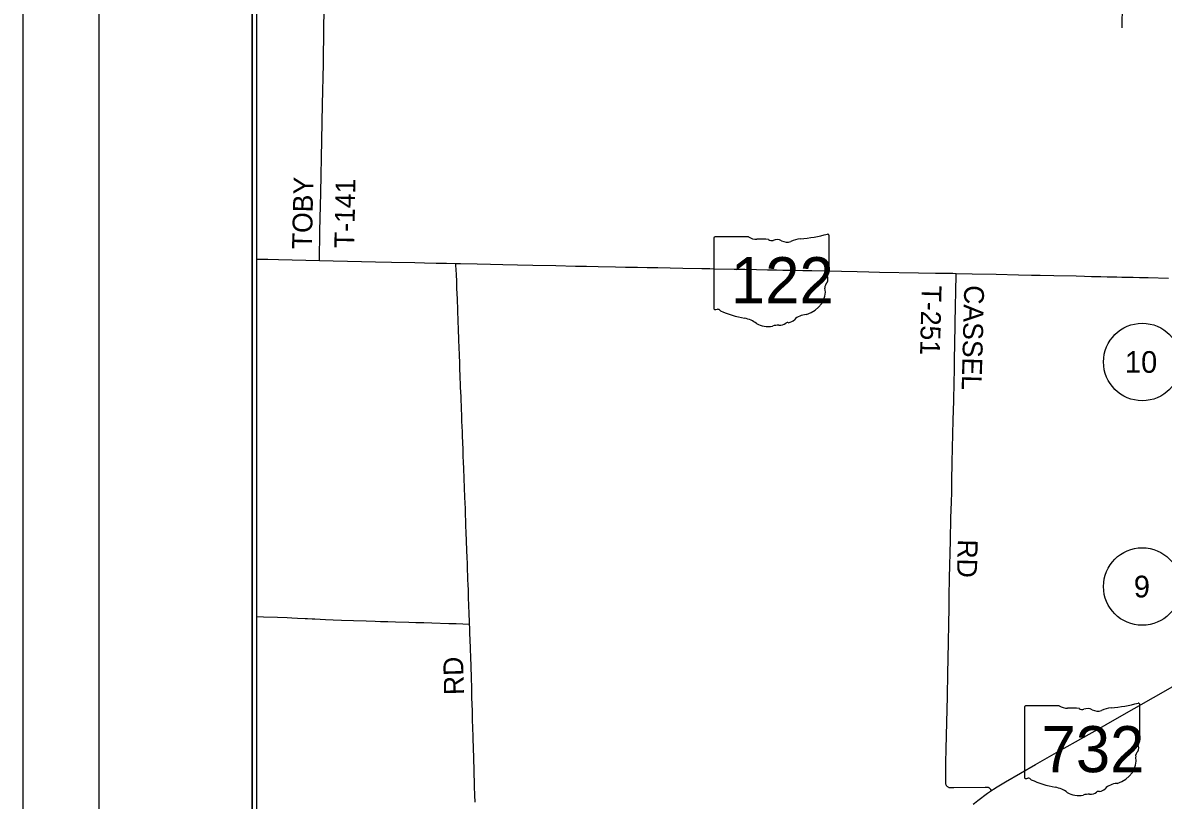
# Model space of a CAD drawing. Extents: x 1341221 to 1914484, y 79347 to 658398.
# Drawn here: x 1341221 to 1374791, y 599399 to 622283 of the extents above; entities that cross this region are included whole.
import ezdxf

# ---------------------------------------------------------------- set-up
doc = ezdxf.new("R2010")
doc.units = 0
for name, color, linetype in [('GM_X_Corporation_Text', 7, 'Continuous'), ('GM_X_County', 7, 'Continuous'), ('GM_X_Major_Lake_Text', 7, 'Continuous'), ('GM_X_Major_River', 7, 'Continuous'), ('GM_X_Major_River_Text', 7, 'Continuous'), ('GM_X_Minor_Lake_Text', 7, 'Continuous'), ('GM_X_Minor_River_Text', 7, 'Continuous'), ('GM_X_State_Location', 7, 'Continuous'), ('GM_X_State_Shield', 7, 'Continuous'), ('GM_X_Township_Text', 7, 'Continuous'), ('GM_X_US_Shield', 7, 'Continuous')]:
    doc.layers.add(name, color=color, linetype=linetype)

msp = doc.modelspace()

# ---------------------------------------------------------------- linework, layer by layer
at = {"layer": 'GM_X_Corporation_Text'}
for p, q in [((1364953, 614951), (1364953, 616029)), ((1361559, 615942), (1361559, 613882)), ((1362586, 615978), (1361593, 615978)), ((1364952, 614951), (1364953, 614951)), ((1370705, 602137), (1370705, 600077)), ((1371733, 602172), (1370739, 602172)), ((1374099, 601146), (1374099, 602223)), ((1374098, 601146), (1374099, 601146))]:
    msp.add_line(p, q, dxfattribs=at)
for centre, major_axis, start_param, end_param in [((1363744, 618787), (3599, 0), 4.814394, 5.042369), ((1364915, 616033), (37.8, 0), 6.141152, 7.989035), ((1361598, 615947), (39.3, 0), 1.712693, 3.28349), ((1362823, 616217), (381, 0), 4.042523, 4.731795), ((1362949, 614821), (1369, 0), 1.404758, 1.657858), ((1363260, 615957), (110, 0), 3.836095, 5.185415), ((1363422, 615719), (229, 0), 0.950623, 2.079405), ((1363717, 616046), (275, 0), 4.081561, 5.145723), ((1364203, 615348), (724, 0), 1.699011, 2.107814), ((1364944, 614872), (58.5, 0), 1.883978, 3.671073), ((1364572, 614735), (351, 0), 5.934695, 6.695948), ((1364912, 614947), (40.4, 0), 5.05454, 6.418171), ((1363945, 614363), (900, 0), 5.101752, 6.440018), ((1365088, 614500), (255, 0), 2.387724, 3.262537), ((1361598, 613877), (39.7, 0), 3.00124, 4.508301), ((1361604, 614088), (303, 0), 4.665946, 4.897461), ((1361666, 613763), (109, 0), 0.519207, 1.627899), ((1363044, 615614), (2599, 0), 4.195997, 4.488961), ((1364325, 613303), (493, 0), 1.647645, 2.488434), ((1362269, 612956), (813, 0), 0.823519, 1.323587), ((1363149, 613753), (516, 0), 4.026481, 4.996735), ((1363447, 613040), (424, 0), 1.495662, 1.94098), ((1363485, 613598), (275, 0), 4.691044, 5.507374), ((1363733, 613399), (77.4, 0), 1.147584, 2.315152), ((1363700, 613682), (291, 0), 4.937069, 5.64225), ((1372890, 604981), (3599, 0), 4.814394, 5.042369), ((1374061, 602228), (37.8, 0), 6.141152, 7.989035), ((1370744, 602141), (39.3, 0), 1.712693, 3.28349), ((1371969, 602412), (381, 0), 4.042523, 4.731795), ((1372096, 601016), (1369, 0), 1.404758, 1.657858), ((1372406, 602152), (110, 0), 3.836095, 5.185415), ((1372568, 601914), (229, 0), 0.950623, 2.079405), ((1372863, 602241), (275, 0), 4.081561, 5.145723), ((1373349, 601543), (724, 0), 1.699011, 2.107814), ((1374090, 601066), (58.5, 0), 1.883978, 3.671073), ((1373718, 600930), (351, 0), 5.934695, 6.695948), ((1374059, 601141), (40.4, 0), 5.05454, 6.418171), ((1373092, 600557), (900, 0), 5.101752, 6.440018), ((1374234, 600695), (255, 0), 2.387724, 3.262537), ((1370745, 600072), (39.7, 0), 3.00124, 4.508301), ((1370751, 600283), (303, 0), 4.665946, 4.897461), ((1370813, 599958), (109, 0), 0.519207, 1.627899), ((1372190, 601809), (2599, 0), 4.195997, 4.488961), ((1371416, 599151), (813, 0), 0.823519, 1.323587), ((1372295, 599947), (516, 0), 4.026481, 4.996735), ((1372593, 599235), (424, 0), 1.495662, 1.94098), ((1372631, 599793), (275, 0), 4.691044, 5.507374), ((1372880, 599594), (77.4, 0), 1.147584, 2.315152), ((1372847, 599877), (291, 0), 4.937069, 5.64225), ((1373471, 599498), (493, 0), 1.647645, 2.488434)]:
    msp.add_ellipse(centre, major_axis=major_axis, ratio=0.8, start_param=start_param, end_param=end_param, dxfattribs=at)
at = {"layer": 'GM_X_County'}
for centre in [(1374174, 612298), (1374174, 605688)]:
    msp.add_circle(centre, 1141, dxfattribs=at)
at = {"layer": 'GM_X_Minor_Lake_Text'}
for points in [[(1343471, 656148), (1347971, 656148), (1347971, 561648), (1343471, 561648)], [(1347971, 656148), (1491971, 656148), (1491971, 561648), (1347971, 561648)], [(1435650, 641695), (1348099, 641695), (1348099, 580425), (1435650, 580425)]]:
    msp.add_lwpolyline(points, close=True, dxfattribs=at)
at = {"layer": 'GM_X_Minor_River_Text'}
msp.add_lwpolyline([(1341221, 559398), (1494221, 559398), (1494221, 658398), (1341221, 658398)], close=True, dxfattribs=at)
at = {"layer": 'GM_X_State_Location'}
for p, q in [((1373403, 614802), (1373423, 614802)), ((1373711, 614796), (1373762, 614796))]:
    msp.add_line(p, q, dxfattribs=at)
for points in [[(1348099, 615327), (1348431, 615321), (1348744, 615314), (1349956, 615283)], [(1349956, 615283), (1350359, 615275), (1350774, 615266), (1351600, 615248), (1352073, 615239), (1352757, 615225), (1353045, 615220), (1353390, 615211), (1353691, 615204), (1353969, 615198), (1354106, 615195), (1354593, 615187), (1354989, 615176), (1355347, 615168), (1355788, 615156), (1356236, 615147), (1356914, 615134), (1357490, 615123), (1357816, 615117), (1358154, 615110), (1358672, 615097), (1358960, 615093), (1359318, 615089), (1359600, 615082), (1359913, 615077), (1360278, 615068), (1360655, 615060), (1361205, 615051), (1361442, 615047)], [(1361442, 615047), (1361576, 615045), (1362164, 615034), (1362478, 615027), (1362817, 615021), (1363143, 615012), (1363405, 615007), (1363597, 615003), (1363897, 614998), (1364185, 614993), (1364447, 614988), (1364844, 614979), (1365323, 614968), (1365784, 614960), (1366123, 614954), (1366443, 614947), (1367588, 614927), (1368086, 614916), (1368598, 614908), (1368699, 614906)], [(1368699, 614906), (1369167, 614897), (1369871, 614882), (1370536, 614867), (1370913, 614858), (1371169, 614853), (1371572, 614844), (1372230, 614830), (1372473, 614823), (1372678, 614818), (1372953, 614813), (1373145, 614809), (1373403, 614802)], [(1373423, 614802), (1373577, 614798), (1373711, 614796)], [(1373762, 614796), (1373905, 614792), (1374090, 614789), (1374346, 614781), (1374947, 614768)], [(1369197, 599284), (1369239, 599316), (1369336, 599389), (1369617, 599601), (1369739, 599687), (1369792, 599722), (1369899, 599790), (1370152, 599941), (1371027, 600446), (1371722, 600842), (1372205, 601120), (1372852, 601483), (1373372, 601772), (1375078, 602744), (1375736, 603114), (1375804, 603153), (1376176, 603363), (1376498, 603548), (1376965, 603813), (1377238, 603969), (1378266, 604560), (1378605, 604754)]]:
    msp.add_lwpolyline(points, dxfattribs=at)
at = {"layer": 'GM_X_State_Shield'}
msp.add_lwpolyline([(1373583, 622133), (1373584, 622196), (1373586, 622363), (1373592, 622600), (1373597, 622741), (1373600, 622916), (1373604, 623056), (1373609, 623174), (1373614, 623347), (1373625, 623774), (1373632, 624099), (1373634, 624190), (1373636, 624273)], dxfattribs=at)
at = {"layer": 'GM_X_Township_Text'}
msp.add_line((1349604, 604745), (1349737, 604739), dxfattribs=at)
for points in [[(1349956, 615283), (1349968, 616145), (1349990, 617280), (1350024, 618829), (1350044, 619881), (1350068, 621073), (1350085, 622141), (1350105, 623129), (1350108, 623348), (1350116, 623891), (1350128, 624506), (1350151, 625514), (1350155, 625698), (1350177, 626717), (1350194, 627898), (1350210, 628758), (1350238, 629801), (1350245, 630358), (1350258, 630899)], [(1369739, 599687), (1369713, 599718), (1369696, 599736), (1369684, 599747), (1369677, 599754), (1369669, 599759), (1369661, 599763), (1369655, 599766), (1369646, 599769), (1369640, 599770), (1369631, 599772), (1369618, 599774), (1369597, 599775), (1369554, 599775), (1368623, 599763), (1368569, 599763), (1368544, 599762), (1368534, 599763), (1368519, 599763), (1368509, 599765), (1368495, 599767), (1368479, 599772), (1368462, 599779), (1368447, 599788), (1368432, 599801), (1368420, 599815), (1368413, 599827), (1368406, 599839), (1368402, 599853), (1368397, 599872), (1368395, 599891), (1368394, 599917), (1368393, 599966), (1368396, 600173), (1368396, 600506), (1368404, 600896), (1368413, 601299), (1368438, 602450), (1368451, 603134), (1368461, 603563), (1368489, 605072), (1368494, 605399), (1368504, 605942), (1368532, 607042), (1368544, 607707), (1368560, 608175), (1368568, 608468), (1368572, 608793), (1368582, 609346), (1368612, 610585), (1368627, 611154), (1368637, 611704), (1368643, 612056), (1368652, 612439), (1368659, 612765), (1368670, 613457), (1368698, 614851), (1368699, 614906)], [(1348099, 604807), (1348308, 604800), (1348723, 604784), (1349005, 604773), (1349139, 604767), (1349309, 604759), (1349532, 604749), (1349604, 604745)], [(1349737, 604739), (1349816, 604734), (1350136, 604720), (1350359, 604710), (1350601, 604701), (1350953, 604689), (1351326, 604675), (1351596, 604667), (1351751, 604663), (1351967, 604656), (1352187, 604649), (1352583, 604637), (1352792, 604631), (1353023, 604625), (1353261, 604618), (1353766, 604602), (1353973, 604596), (1354177, 604590), (1354372, 604585)]]:
    msp.add_lwpolyline(points, dxfattribs=at)
at = {"layer": 'GM_X_US_Shield'}
msp.add_lwpolyline([(1354536, 599343), (1354530, 599542), (1354522, 599803), (1354518, 599939), (1354511, 600163), (1354505, 600348), (1354499, 600554), (1354494, 600710), (1354489, 600865), (1354484, 601012), (1354480, 601141), (1354474, 601338), (1354470, 601459), (1354467, 601566), (1354463, 601721), (1354458, 601870), (1354454, 602016), (1354443, 602425), (1354440, 602587), (1354435, 602782), (1354432, 602923), (1354425, 603100), (1354420, 603247), (1354417, 603372), (1354416, 603438), (1354413, 603508), (1354412, 603559), (1354409, 603615), (1354401, 603836), (1354388, 604160), (1354384, 604263), (1354380, 604364), (1354376, 604472), (1354372, 604585), (1354370, 604663), (1354362, 604889), (1354353, 605136), (1354345, 605352), (1354336, 605583), (1354329, 605750), (1354324, 605885), (1354317, 606055), (1354315, 606128), (1354307, 606349), (1354299, 606565), (1354293, 606733), (1354281, 607050), (1354273, 607257), (1354265, 607493), (1354260, 607619), (1354254, 607803), (1354249, 607957), (1354239, 608173), (1354234, 608285), (1354229, 608402), (1354224, 608519), (1354221, 608603), (1354211, 608854), (1354199, 609170), (1354194, 609341), (1354186, 609538), (1354180, 609726), (1354165, 610120), (1354161, 610243), (1354154, 610397), (1354148, 610559), (1354141, 610739), (1354135, 610895), (1354122, 611272), (1354110, 611559), (1354095, 611926), (1354090, 612059), (1354082, 612252), (1354073, 612516), (1354065, 612716), (1354057, 612948), (1354044, 613275), (1354036, 613492), (1354025, 613823), (1354012, 614156), (1354000, 614465), (1353995, 614583), (1353993, 614678), (1353986, 614861), (1353978, 615023), (1353972, 615140), (1353971, 615173), (1353969, 615198)], dxfattribs=at)

# ---------------------------------------------------------------- texts
at = {"layer": 'GM_X_Corporation_Text'}
for s, p in [('122', (1362064, 614027)), ('732', (1371210, 600222))]:
    msp.add_text(s, height=1357.4, dxfattribs=at).set_placement(p)
at = {"layer": 'GM_X_County'}
for s, height, p in [('10', 638.8, (1373665, 611979)), ('9', 639, (1373926, 605368))]:
    msp.add_text(s, height=height, dxfattribs=at).set_placement(p)
at = {"layer": 'GM_X_Major_Lake_Text'}
msp.add_text('RD', height=585, rotation=91.4816, dxfattribs=at).set_placement((1354208, 602501))
at = {"layer": 'GM_X_Major_River'}
for s, p in [('s', (1363218, 614775)), ('r', (1363218, 614775)), ('s', (1372364, 600970)), ('r', (1372364, 600970))]:
    msp.add_text(s, height=1.95, dxfattribs=at).set_placement(p)
for s, p in [('122', (1362529, 614633)), ('732', (1371676, 600828))]:
    msp.add_text(s, height=1.95, rotation=0, dxfattribs=at).set_placement(p)
at = {"layer": 'GM_X_Major_River_Text'}
for s, rotation, p in [('TOBY', 88.7382, (1349730, 615613)), ('T-141', 88.8765, (1350975, 615648)), ('T-251', 268.5962, (1367683, 614552)), ('CASSEL', 268.5217, (1368937, 614564)), ('RD', 268.5189, (1368748, 607082))]:
    msp.add_text(s, height=585, rotation=rotation, dxfattribs=at).set_placement(p)

doc.saveas('drawing.dxf')
